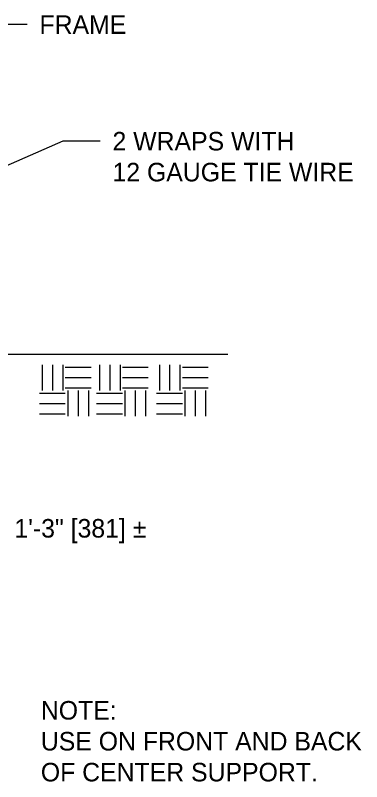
# Model space of a CAD drawing. Extents: x 49991.4 to 50021, y 49987.6 to 50011.4.
# Drawn here: x 50009.746 to 50010.867, y 49991.923 to 49994.402 of the extents above; entities that cross this region are included whole.
import ezdxf

# ---------------------------------------------------------------- set-up
doc = ezdxf.new("R2010")
doc.units = 0
for name, color, linetype in [('Level 1', 7, 'Continuous'), ('Level 2', 7, 'Continuous'), ('Level 3', 7, 'Continuous')]:
    doc.layers.add(name, color=color, linetype=linetype)

msp = doc.modelspace()

# ---------------------------------------------------------------- linework, layer by layer
at = {"layer": 'Level 1'}
for p, q in [((50010.4337, 49993.3052), (50008.3401, 49993.3052)), ((50009.8334, 49993.2713), (50009.8334, 49993.1879)), ((50009.8667, 49993.2713), (50009.8667, 49993.1879)), ((50009.9001, 49993.2713), (50009.9001, 49993.1879)), ((50009.9078, 49993.2635), (50009.9912, 49993.2635)), ((50010.0183, 49993.2713), (50010.0183, 49993.1879)), ((50010.0516, 49993.2713), (50010.0516, 49993.1879)), ((50010.085, 49993.2713), (50010.085, 49993.1879)), ((50010.0927, 49993.2635), (50010.1761, 49993.2635)), ((50010.2121, 49993.2713), (50010.2121, 49993.1879)), ((50010.2454, 49993.2713), (50010.2454, 49993.1879)), ((50010.2788, 49993.2713), (50010.2788, 49993.1879)), ((50010.2865, 49993.2635), (50010.3699, 49993.2635)), ((50009.9078, 49993.2302), (50009.9912, 49993.2302)), ((50010.0927, 49993.2302), (50010.1761, 49993.2302)), ((50010.2865, 49993.2302), (50010.3699, 49993.2302)), ((50009.8244, 49993.1801), (50009.9078, 49993.1801)), ((50009.9078, 49993.1968), (50009.9912, 49993.1968)), ((50009.9161, 49993.1885), (50009.9161, 49993.1051)), ((50009.9495, 49993.1885), (50009.9495, 49993.1051)), ((50009.9829, 49993.1885), (50009.9829, 49993.1051)), ((50010.0093, 49993.1801), (50010.0927, 49993.1801)), ((50010.0927, 49993.1968), (50010.1761, 49993.1968)), ((50010.101, 49993.1885), (50010.101, 49993.1051)), ((50010.1344, 49993.1885), (50010.1344, 49993.1051)), ((50010.1678, 49993.1885), (50010.1678, 49993.1051)), ((50010.2031, 49993.1801), (50010.2865, 49993.1801)), ((50010.2865, 49993.1968), (50010.3699, 49993.1968)), ((50010.2948, 49993.1885), (50010.2948, 49993.1051)), ((50010.3282, 49993.1885), (50010.3282, 49993.1051)), ((50010.3616, 49993.1885), (50010.3616, 49993.1051)), ((50009.8244, 49993.1468), (50009.9078, 49993.1468)), ((50010.0093, 49993.1468), (50010.0927, 49993.1468)), ((50010.2031, 49993.1468), (50010.2865, 49993.1468)), ((50009.8244, 49993.1134), (50009.9078, 49993.1134)), ((50010.0093, 49993.1134), (50010.0927, 49993.1134)), ((50010.2031, 49993.1134), (50010.2865, 49993.1134))]:
    msp.add_line(p, q, dxfattribs=at)
at = {"layer": 'Level 3'}
for p, q in [((50009.7844, 49994.3716), (50009.4785, 49994.3716)), ((50009.8997, 49993.9946), (50009.5347, 49993.8344)), ((50010.0206, 49993.9946), (50009.8997, 49993.9946))]:
    msp.add_line(p, q, dxfattribs=at)

# ---------------------------------------------------------------- texts
at = {"layer": 'Level 2'}
for s, p in [('FRAME', (50009.8244, 49994.3416)), ('2 WRAPS WITH', (50010.0606, 49993.9646)), ('12 GAUGE TIE WIRE', (50010.0606, 49993.8646)), ('1\'-3" [381] ±', (50009.7432, 49992.7127)), ('NOTE:', (50009.8288, 49992.1242)), ('USE ON FRONT AND BACK', (50009.8288, 49992.0242)), ('OF CENTER SUPPORT.', (50009.8288, 49991.9242))]:
    msp.add_text(s, height=0.06, dxfattribs=at).set_placement(p)

doc.saveas('drawing.dxf')
